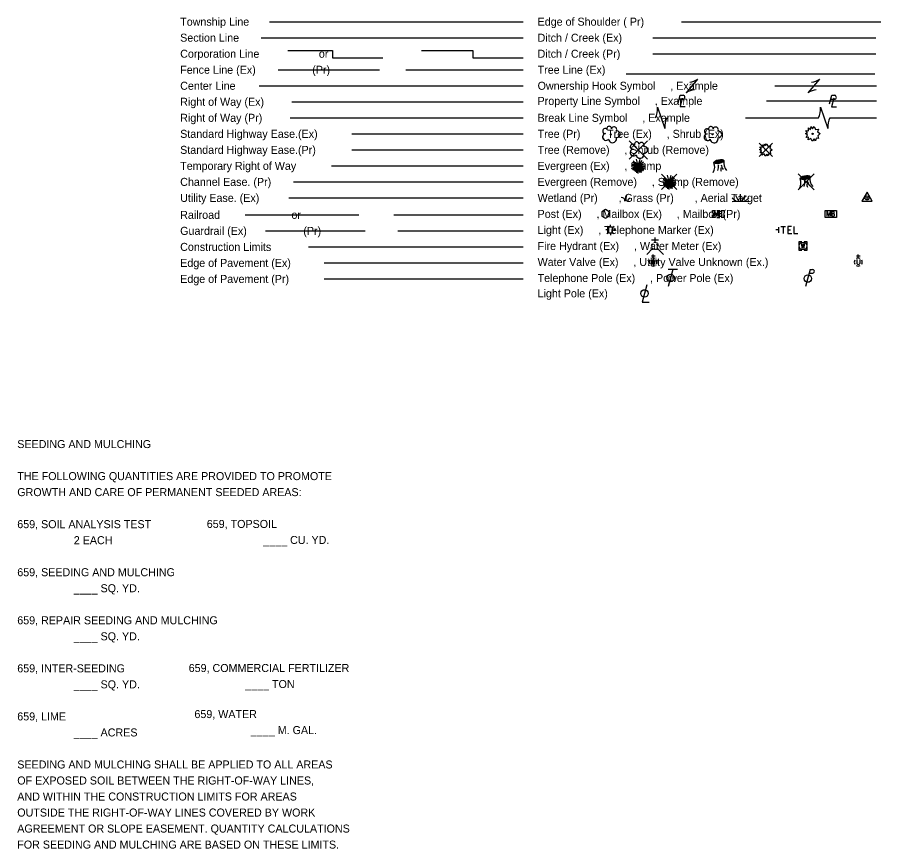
# Model space of a CAD drawing. Extents: x -9 to 100, y -25 to 48.
# Drawn here: x 38.51 to 53.61, y -9.25 to 5.28 of the extents above; entities that cross this region are included whole.
import ezdxf

# ---------------------------------------------------------------- set-up
doc = ezdxf.new("R2010")
doc.units = 0
doc.layers.add('SH_Text', color=7, linetype='Continuous')

msp = doc.modelspace()

# ---------------------------------------------------------------- linework, layer by layer
at = {"layer": 'SH_Text'}
for p, q in [((42.921, 5.205), (47.362, 5.205)), ((50.129, 5.205), (53.612, 5.205)), ((42.779, 4.925), (47.362, 4.925)), ((49.628, 4.925), (53.528, 4.925)), ((43.243, 4.701), (44.025, 4.701)), ((44.025, 4.701), (44.025, 4.575)), ((44.025, 4.575), (44.906, 4.575)), ((49.628, 4.645), (53.528, 4.645)), ((43.076, 4.365), (44.849, 4.365)), ((45.306, 4.365), (47.362, 4.365)), ((49.161, 4.295), (53.511, 4.295)), ((42.744, 4.085), (47.362, 4.085)), ((50.213, 3.962), (50.413, 4.202)), ((50.313, 4.082), (50.313, 4.082)), ((51.759, 4.085), (53.541, 4.085)), ((52.345, 3.962), (52.545, 4.202)), ((52.445, 4.082), (52.445, 4.082)), ((43.312, 3.805), (47.362, 3.805)), ((50.089, 3.854), (50.154, 3.854)), ((50.129, 3.822), (50.129, 3.822)), ((51.617, 3.82), (53.541, 3.82)), ((52.738, 3.85), (52.802, 3.85)), ((52.778, 3.818), (52.778, 3.818)), ((49.706, 3.709), (49.836, 3.34)), ((52.559, 3.709), (52.689, 3.34)), ((43.284, 3.525), (47.362, 3.525)), ((49.771, 3.525), (49.771, 3.525)), ((51.248, 3.525), (52.524, 3.525)), ((52.624, 3.524), (52.624, 3.524)), ((52.724, 3.525), (53.541, 3.525)), ((44.362, 3.245), (47.362, 3.245)), ((49.214, 3.125), (49.535, 2.804)), ((49.535, 3.125), (49.214, 2.804)), ((51.485, 3.08), (51.717, 2.849)), ((51.717, 3.08), (51.485, 2.849)), ((44.362, 2.965), (47.362, 2.965)), ((49.374, 2.965), (49.374, 2.965)), ((51.601, 2.965), (51.601, 2.965)), ((49.372, 2.684), (49.275, 2.742)), ((49.372, 2.684), (49.285, 2.771)), ((49.372, 2.684), (49.341, 2.8)), ((49.372, 2.684), (49.404, 2.802)), ((49.372, 2.684), (49.439, 2.781)), ((49.372, 2.684), (49.464, 2.754)), ((49.372, 2.684), (49.491, 2.724)), ((44.008, 2.685), (47.362, 2.685)), ((49.249, 2.684), (49.372, 2.684)), ((49.372, 2.684), (49.262, 2.714)), ((49.372, 2.684), (49.265, 2.645)), ((49.372, 2.684), (49.273, 2.627)), ((49.372, 2.684), (49.275, 2.609)), ((49.372, 2.684), (49.299, 2.598)), ((49.372, 2.684), (49.314, 2.584)), ((49.372, 2.684), (49.331, 2.576)), ((49.372, 2.684), (49.341, 2.563)), ((49.372, 2.684), (49.359, 2.57)), ((49.372, 2.684), (49.485, 2.687)), ((49.372, 2.553), (49.372, 2.684)), ((49.372, 2.684), (49.395, 2.568)), ((49.372, 2.684), (49.421, 2.568)), ((49.372, 2.684), (49.436, 2.589)), ((49.372, 2.684), (49.462, 2.596)), ((49.372, 2.684), (49.468, 2.62)), ((49.372, 2.684), (49.484, 2.636)), ((49.372, 2.684), (49.493, 2.66)), ((50.8, 2.685), (50.8, 2.685)), ((49.781, 2.538), (50.049, 2.271)), ((50.049, 2.538), (49.781, 2.271)), ((49.915, 2.405), (49.805, 2.434)), ((49.915, 2.405), (49.817, 2.462)), ((49.915, 2.405), (49.828, 2.492)), ((49.915, 2.405), (49.884, 2.52)), ((49.915, 2.405), (49.946, 2.522)), ((49.915, 2.405), (49.981, 2.502)), ((49.915, 2.405), (50.006, 2.475)), ((49.915, 2.405), (50.033, 2.445)), ((52.169, 2.544), (52.447, 2.266)), ((52.447, 2.544), (52.169, 2.266)), ((43.345, 2.405), (47.362, 2.405)), ((49.791, 2.405), (49.915, 2.405)), ((49.915, 2.405), (49.808, 2.366)), ((49.915, 2.405), (49.815, 2.348)), ((49.915, 2.405), (49.817, 2.33)), ((49.915, 2.405), (49.841, 2.318)), ((49.915, 2.405), (49.857, 2.304)), ((49.915, 2.405), (49.873, 2.296)), ((49.915, 2.405), (49.883, 2.283)), ((49.915, 2.405), (49.901, 2.29)), ((49.915, 2.405), (50.028, 2.407)), ((49.915, 2.274), (49.915, 2.405)), ((49.915, 2.405), (49.938, 2.289)), ((49.915, 2.405), (49.963, 2.288)), ((49.915, 2.405), (49.978, 2.31)), ((49.915, 2.405), (50.005, 2.317)), ((49.915, 2.405), (50.01, 2.341)), ((49.915, 2.405), (50.026, 2.356)), ((49.915, 2.405), (50.036, 2.381)), ((49.915, 2.405), (49.915, 2.405)), ((52.308, 2.405), (52.308, 2.405)), ((52.308, 2.405), (52.308, 2.405)), ((43.262, 2.125), (47.362, 2.125)), ((51.082, 2.063), (51.013, 2.121)), ((51.13, 2.064), (51.078, 2.17)), ((51.16, 2.065), (51.158, 2.19)), ((51.19, 2.065), (51.239, 2.173)), ((51.239, 2.066), (51.305, 2.125)), ((51.014, 2.062), (51.306, 2.067)), ((42.5, 1.829), (44.486, 1.829)), ((45.096, 1.829), (47.362, 1.829)), ((50.746, 1.906), (50.796, 1.906)), ((50.772, 1.845), (50.772, 1.845)), ((52.739, 1.845), (52.739, 1.845)), ((50.746, 1.783), (50.796, 1.783)), ((42.855, 1.549), (44.597, 1.549)), ((45.167, 1.549), (47.362, 1.549)), ((48.834, 1.565), (48.808, 1.565)), ((48.838, 1.613), (48.82, 1.632)), ((48.838, 1.516), (48.82, 1.497)), ((48.887, 1.629), (48.887, 1.655)), ((48.887, 1.565), (48.887, 1.565)), ((48.953, 1.632), (48.935, 1.613)), ((48.953, 1.497), (48.935, 1.516)), ((48.965, 1.565), (48.939, 1.565)), ((51.828, 1.565), (51.778, 1.565)), ((51.828, 1.515), (51.828, 1.615)), ((48.887, 1.501), (48.887, 1.474)), ((49.726, 1.388), (49.606, 1.388)), ((49.666, 1.345), (49.666, 1.431)), ((43.606, 1.269), (47.362, 1.269)), ((49.624, 1.242), (49.52, 1.138)), ((49.666, 1.285), (49.666, 1.285)), ((49.666, 1.285), (49.666, 1.285)), ((49.708, 1.242), (49.812, 1.138)), ((52.253, 1.285), (52.253, 1.285)), ((49.666, 1.106), (49.603, 1.106)), ((49.634, 1.075), (49.634, 1.138)), ((53.251, 1.105), (53.188, 1.105)), ((53.22, 1.074), (53.22, 1.137)), ((43.879, 0.989), (47.362, 0.989)), ((49.634, 1.005), (49.634, 1.005)), ((53.192, 1.047), (53.192, 0.978)), ((53.22, 1.004), (53.22, 1.004)), ((53.247, 1.047), (53.247, 0.978)), ((50.058, 0.875), (49.898, 0.875)), ((49.978, 0.875), (49.898, 0.575)), ((52.38, 0.875), (52.299, 0.575)), ((52.363, 0.811), (52.422, 0.811)), ((52.38, 0.875), (52.422, 0.875)), ((43.879, 0.709), (47.362, 0.709))]:
    msp.add_line(p, q, dxfattribs=at)
for points in [[(45.579, 4.701), (46.482, 4.701), (46.477, 4.575), (47.362, 4.575)], [(50.068, 3.774), (50.107, 3.922), (50.159, 3.922)], [(50.142, 3.87), (50.103, 3.723), (50.19, 3.723)], [(52.717, 3.77), (52.756, 3.918), (52.807, 3.918)], [(52.791, 3.866), (52.751, 3.719), (52.839, 3.719)], [(52.418, 3.335), (52.448, 3.372), (52.469, 3.319), (52.523, 3.328), (52.506, 3.278), (52.553, 3.248), (52.511, 3.211), (52.523, 3.165), (52.485, 3.169), (52.469, 3.123), (52.448, 3.158), (52.414, 3.117), (52.392, 3.161), (52.341, 3.14), (52.351, 3.187), (52.31, 3.183), (52.334, 3.222), (52.296, 3.251), (52.333, 3.264), (52.302, 3.304), (52.349, 3.298), (52.347, 3.35), (52.385, 3.322), (52.395, 3.371), (52.418, 3.335)], [(51.597, 3.041), (51.623, 3.073), (51.64, 3.028), (51.687, 3.036), (51.672, 2.993), (51.713, 2.967), (51.676, 2.936), (51.687, 2.897), (51.655, 2.9), (51.641, 2.861), (51.623, 2.891), (51.594, 2.856), (51.576, 2.894), (51.532, 2.875), (51.541, 2.915), (51.506, 2.912), (51.526, 2.946), (51.494, 2.97), (51.525, 2.981), (51.499, 3.015), (51.539, 3.01), (51.537, 3.054), (51.569, 3.03), (51.578, 3.072), (51.597, 3.041)], [(48.734, 1.807), (48.799, 1.77), (48.864, 1.807), (48.864, 1.882), (48.799, 1.92), (48.734, 1.882), (48.734, 1.807)], [(50.672, 1.857), (50.672, 1.906), (50.72, 1.906)], [(50.72, 1.783), (50.672, 1.783), (50.672, 1.832)], [(50.707, 1.805), (50.707, 1.885), (50.736, 1.805), (50.764, 1.885), (50.764, 1.805)], [(50.823, 1.848), (50.826, 1.851), (50.828, 1.853), (50.829, 1.855), (50.83, 1.856), (50.831, 1.859), (50.832, 1.861), (50.833, 1.865), (50.833, 1.867), (50.833, 1.869), (50.832, 1.873), (50.831, 1.876), (50.829, 1.879), (50.826, 1.881), (50.824, 1.883), (50.822, 1.883), (50.819, 1.885), (50.788, 1.885), (50.788, 1.805), (50.823, 1.805), (50.827, 1.807), (50.831, 1.81), (50.834, 1.815), (50.836, 1.821), (50.837, 1.827), (50.837, 1.83), (50.836, 1.834), (50.833, 1.84), (50.83, 1.844), (50.823, 1.848), (50.788, 1.848)], [(50.822, 1.906), (50.872, 1.906), (50.872, 1.857)], [(50.872, 1.832), (50.872, 1.783), (50.822, 1.783)], [(52.674, 1.805), (52.674, 1.885), (52.703, 1.805), (52.731, 1.885), (52.731, 1.805)], [(52.79, 1.848), (52.793, 1.851), (52.795, 1.853), (52.796, 1.855), (52.797, 1.856), (52.798, 1.859), (52.799, 1.861), (52.8, 1.865), (52.8, 1.867), (52.8, 1.869), (52.799, 1.873), (52.798, 1.876), (52.796, 1.879), (52.793, 1.881), (52.791, 1.883), (52.789, 1.883), (52.786, 1.885), (52.755, 1.885), (52.755, 1.805), (52.79, 1.805), (52.794, 1.807), (52.798, 1.81), (52.801, 1.815), (52.803, 1.821), (52.804, 1.827), (52.804, 1.83), (52.803, 1.834), (52.8, 1.84), (52.797, 1.844), (52.79, 1.848), (52.755, 1.848)], [(51.868, 1.627), (51.946, 1.627)], [(51.908, 1.627), (51.908, 1.502)], [(52.053, 1.627), (51.986, 1.627), (51.986, 1.502), (52.058, 1.502)], [(51.986, 1.565), (52.034, 1.565)], [(52.093, 1.627), (52.093, 1.502), (52.161, 1.502)], [(52.233, 1.36), (52.178, 1.36), (52.178, 1.305)], [(52.328, 1.305), (52.328, 1.36), (52.273, 1.36)], [(52.178, 1.265), (52.178, 1.21), (52.233, 1.21)], [(52.22, 1.33), (52.236, 1.24), (52.253, 1.33), (52.27, 1.24), (52.286, 1.33)], [(52.273, 1.21), (52.328, 1.21), (52.328, 1.265)], [(49.603, 1.046), (49.619, 0.959), (49.634, 1.046), (49.65, 0.959), (49.666, 1.046)], [(49.52, 0.603), (49.441, 0.304), (49.56, 0.304)]]:
    msp.add_lwpolyline(points, dxfattribs=at)
for points in [[(53.284, 2.066), (53.464, 2.066), (53.374, 2.227)], [(52.639, 1.906), (52.839, 1.906), (52.839, 1.783), (52.639, 1.783)], [(48.853, 1.515), (48.92, 1.515), (48.92, 1.615), (48.853, 1.615)]]:
    msp.add_lwpolyline(points, close=True, dxfattribs=at)
for centre, radius in [((48.894, 3.236), 0.0084), ((50.671, 3.233), 0.0072), ((52.422, 3.245), 0.0115), ((49.374, 2.965), 0.0072), ((51.601, 2.965), 0.00979), ((53.374, 2.124), 0.035), ((53.374, 2.124), 0.008), ((52.253, 1.285), 0.0675), ((49.938, 0.725), 0.065), ((52.337, 0.715), 0.065), ((49.481, 0.456), 0.065)]:
    msp.add_circle(centre, radius, dxfattribs=at)
for centre, radius, start, end in [((50.255, 4.417), 0.267, 273.6945, 306.337), ((52.387, 4.417), 0.267, 273.6945, 306.337), ((50.371, 3.747), 0.267, 93.6945, 126.337), ((52.503, 3.747), 0.267, 93.6945, 126.337), ((50.154, 3.888), 0.0345, 270.471, 81.3281), ((52.802, 3.884), 0.0345, 270.471, 81.3281), ((49.374, 3.676), 0.334, 332.9422, 5.5848), ((52.227, 3.676), 0.334, 332.9422, 5.5848), ((50.168, 3.373), 0.334, 152.9422, 185.5848), ((53.021, 3.373), 0.334, 152.9422, 185.5848), ((48.794, 3.292), 0.0441, 39.0625, 279.5412), ((48.864, 3.337), 0.0395, 354.0047, 205.9741), ((48.949, 3.321), 0.0466, 323.83, 165.0376), ((50.572, 3.289), 0.0441, 39.0625, 279.5412), ((50.641, 3.334), 0.0395, 354.0047, 205.9741), ((50.726, 3.318), 0.0466, 323.83, 165.0376), ((48.808, 3.19), 0.0592, 96.1722, 320.5737), ((48.922, 3.158), 0.0685, 184.9476, 19.4572), ((48.998, 3.238), 0.0574, 259.1453, 101.4596), ((50.585, 3.187), 0.0592, 96.1722, 320.5737), ((50.699, 3.155), 0.0685, 184.9476, 19.4572), ((50.775, 3.234), 0.0574, 259.1453, 101.4596), ((49.275, 3.02), 0.0441, 39.0625, 279.5412), ((49.345, 3.066), 0.0395, 354.0047, 205.9741), ((49.429, 3.049), 0.0466, 323.83, 165.0376), ((49.478, 2.966), 0.0574, 259.1453, 101.4596), ((49.289, 2.918), 0.0592, 96.1722, 320.5737), ((49.403, 2.886), 0.0685, 184.9476, 19.4572), ((50.509, 2.667), 0.2, 331.5338, 20.9269), ((51.081, 2.742), 0.215, 171.4106, 219.9194), ((50.524, 2.686), 0.253, 340.7938, 3.5481), ((50.996, 2.645), 0.182, 178.7926, 197.1224), ((51.126, 2.787), 0.316, 194.9653, 212.1216), ((52.016, 2.387), 0.2, 331.5338, 20.9269), ((52.032, 2.406), 0.253, 340.7938, 3.5481), ((52.633, 2.507), 0.316, 194.9653, 212.1216), ((52.588, 2.462), 0.215, 171.4106, 219.9194), ((52.503, 2.365), 0.182, 178.7926, 197.1224), ((49.666, 1.285), 0.06, 140.021, 184.0629), ((49.666, 1.285), 0.06, 211.8788, 255.8479), ((49.666, 1.285), 0.06, 68.1395, 112.038), ((49.666, 1.285), 0.06, 283.8239, 329.9097), ((49.666, 1.285), 0.06, 356.0165, 39.9889), ((49.634, 1.005), 0.07, 60.0184, 120.0157), ((53.22, 1.004), 0.07, 60.0184, 120.0157), ((49.634, 1.005), 0.07, 150.0184, 209.9816), ((49.634, 1.005), 0.07, 239.9843, 299.9816), ((49.634, 1.005), 0.07, 330.0184, 29.9816), ((53.22, 1.004), 0.07, 150.0184, 209.9816), ((53.22, 1.004), 0.07, 239.9843, 299.9816), ((53.22, 0.99), 0.03, 205.1924, 334.8076), ((53.22, 1.004), 0.07, 330.0184, 29.9816), ((52.423, 0.843), 0.0319, 268.8767, 91.1233)]:
    msp.add_arc(centre, radius, start, end, dxfattribs=at)
for centre, major_axis in [((50.782, 2.76), (0.0868, 0.0187)), ((50.782, 2.76), (0.0651, 0.0141)), ((50.782, 2.76), (0.0488, 0.0105)), ((50.782, 2.76), (0.0275, 0.0059)), ((50.782, 2.76), (0.0154, 0.0033)), ((52.289, 2.48), (0.0868, 0.0187)), ((52.289, 2.48), (0.0651, 0.0141)), ((52.289, 2.48), (0.0488, 0.0105)), ((52.289, 2.48), (0.0275, 0.0059)), ((52.289, 2.48), (0.0154, 0.0033))]:
    msp.add_ellipse(centre, major_axis=major_axis, ratio=0.36865, dxfattribs=at)
for points in [[(49.076, 2.14), (49.117, 2.122), (49.135, 2.069)], [(49.163, 2.073), (49.163, 2.12), (49.169, 2.165), (49.178, 2.186)], [(49.191, 2.066), (49.203, 2.104), (49.232, 2.128)]]:
    msp.add_spline(points, degree=3, dxfattribs=at)

# ---------------------------------------------------------------- texts
for s, p in [('Township Line', (41.362, 5.135)), ('Edge of Shoulder ( Pr)', (47.612, 5.135)), ('Section Line', (41.362, 4.855)), ('Ditch / Creek (Ex)', (47.612, 4.855)), ('Corporation Line                    or', (41.362, 4.575)), ('Ditch / Creek (Pr)', (47.612, 4.575)), ('Fence Line (Ex)                   (Pr)', (41.362, 4.295)), ('Tree Line (Ex)', (47.612, 4.295)), ('Center Line', (41.362, 4.015)), ('Ownership Hook Symbol     , Example', (47.612, 4.015)), ('Right of Way (Ex)', (41.362, 3.735)), ('Property Line Symbol     , Example', (47.612, 3.75)), ('Right of Way (Pr)', (41.362, 3.455)), ('Break Line Symbol     , Example', (47.612, 3.455)), ('Standard Highway Ease.(Ex)', (41.362, 3.175)), ('Tree (Pr)       , Tree (Ex)     , Shrub (Ex)', (47.612, 3.175)), ('Standard Highway Ease.(Pr)', (41.362, 2.895)), ('Tree (Remove)     , Shrub (Remove)', (47.612, 2.895)), ('Temporary Right of Way', (41.362, 2.615)), ('Evergreen (Ex)     , Stump ', (47.612, 2.615)), ('Channel Ease. (Pr)', (41.362, 2.335)), ('Evergreen (Remove)     , Stump (Remove)', (47.612, 2.335)), ('Utility Ease. (Ex)', (41.362, 2.055)), ('Wetland (Pr)       , Grass (Pr)       , Aerial Target    ', (47.612, 2.055)), ('Railroad                        or', (41.362, 1.759)), ('Post (Ex)     , Mailbox (Ex)     , Mailbox (Pr)', (47.612, 1.775)), ('Guardrail (Ex)                   (Pr)', (41.362, 1.479)), ('Light (Ex)     , Telephone Marker (Ex)     ', (47.612, 1.495)), ('Fire Hydrant (Ex)     , Water Meter (Ex)', (47.612, 1.215)), ('Construction Limits', (41.362, 1.199)), ('Edge of Pavement (Ex)', (41.362, 0.919)), ('Water Valve (Ex)     , Utility Valve Unknown (Ex.)', (47.612, 0.935)), ('Edge of Pavement (Pr)', (41.362, 0.639)), ('Telephone Pole (Ex)     , Power Pole (Ex)', (47.612, 0.655)), ('Light Pole (Ex)     ', (47.612, 0.387)), ('SEEDING AND MULCHING', (38.513, -2.247)), ('THE FOLLOWING QUANTITIES ARE PROVIDED TO PROMOTE', (38.513, -2.807)), ('GROWTH AND CARE OF PERMANENT SEEDED AREAS:', (38.513, -3.087)), ('659, SOIL ANALYSIS TEST', (38.513, -3.647)), ('659, TOPSOIL', (41.827, -3.643)), ('                   2 EACH', (38.513, -3.927)), ('                   ____ CU. YD.', (41.827, -3.923)), ('659, SEEDING AND MULCHING', (38.513, -4.487)), ('                   ____ SQ. YD.', (38.513, -4.767)), ('659, REPAIR SEEDING AND MULCHING', (38.513, -5.327)), ('                   ____ SQ. YD.', (38.513, -5.607)), ('659, INTER-SEEDING', (38.513, -6.167)), ('659, COMMERCIAL FERTILIZER', (41.511, -6.161)), ('                   ____ SQ. YD.', (38.513, -6.447)), ('                   ____ TON', (41.511, -6.441)), ('659, LIME', (38.513, -7.007)), ('659, WATER', (41.611, -6.966)), ('                   ____ ACRES', (38.513, -7.287)), ('                   ____ M. GAL.', (41.611, -7.246)), ('SEEDING AND MULCHING SHALL BE APPLIED TO ALL AREAS', (38.513, -7.847)), ('OF EXPOSED SOIL BETWEEN THE RIGHT-OF-WAY LINES,', (38.513, -8.127)), ('AND WITHIN THE CONSTRUCTION LIMITS FOR AREAS', (38.513, -8.407)), ('OUTSIDE THE RIGHT-OF-WAY LINES COVERED BY WORK', (38.513, -8.687)), ('AGREEMENT OR SLOPE EASEMENT. QUANTITY CALCULATIONS', (38.513, -8.967)), ('FOR SEEDING AND MULCHING ARE BASED ON THESE LIMITS.', (38.513, -9.247))]:
    msp.add_text(s, height=0.14, dxfattribs=at).set_placement(p)

doc.saveas('drawing.dxf')
